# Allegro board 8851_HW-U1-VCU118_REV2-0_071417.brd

Outline 241.3 x 175.95 mm; copper layers: TOP, 02_GND, 03_SIG1, 04_GND, 05_SIG2, 06_GND, 07_SIG3, 08_GND, 09_PWR1, 10_GND, 11_PWR2, 12_PWR3, 13_GND, 14_SIG4, 15_GND, 16_SIG5, 17_GND, 18_SIG6, 19_GND, 20_SIG7, 21_GND, BOTTOM. Coordinates in mm from the lower left corner of the outline.
Outline path: 0,175.95 0,4.47 15.01,4.47 15.01,12.73 33.35,12.73 33.35,4.5 41.35,4.5 41.35,10.92 arc(43.18,12.75) 45.01,10.92 45.01,0.51 45.52,0 55.69,0 56.2,0.51 56.2,7.45 arc(57.15,8.41) 58.1,7.45 58.1,0.51 58.61,0 128.8,0 129.31,0.51 129.31,12.73 241.3,12.73 241.3,175.95 0,175.95

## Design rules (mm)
constraint set DEFAULT: min track width 0.152
net group 55N3111: nets 55N3111 VCC1V8_FET_SWITCH
net group 57N3711: nets 57N3711 VCC1V2_FET_SWITCH
net group DIFF_DX: nets DXN DXP
net group ENET_TD_A: nets ENET_TD_A_N ENET_TD_A_P
net group ENET_TD_B: nets ENET_TD_B_N ENET_TD_B_P
net group ENET_TD_C: nets ENET_TD_C_N ENET_TD_C_P
net group ENET_TD_D: nets ENET_TD_D_N ENET_TD_D_P
net group ETH_SGMII_CLK_PAIR: nets CLK_125MHZ_N CLK_125MHZ_P
net group FMCP_HSPC_GBT0_0: nets FMCP_HSPC_GBT0_0_N FMCP_HSPC_GBT0_0_P
net group FMCP_HSPC_GBT0_0_C: nets FMCP_HSPC_GBT0_0_C_N FMCP_HSPC_GBT0_0_C_P
net group FMCP_HSPC_GBT0_1: nets FMCP_HSPC_GBT0_1_N FMCP_HSPC_GBT0_1_P
net group FMCP_HSPC_GBT0_1_C: nets FMCP_HSPC_GBT0_1_C_N FMCP_HSPC_GBT0_1_C_P
net group FMCP_HSPC_GBT1_0: nets FMCP_HSPC_GBT1_0_N FMCP_HSPC_GBT1_0_P
net group FMCP_HSPC_GBT1_0_C: nets FMCP_HSPC_GBT1_0_C_N FMCP_HSPC_GBT1_0_C_P
net group FMCP_HSPC_GBT1_1: nets FMCP_HSPC_GBT1_1_N FMCP_HSPC_GBT1_1_P
net group FMCP_HSPC_GBT1_1_C: nets FMCP_HSPC_GBT1_1_C_N FMCP_HSPC_GBT1_1_C_P
net group FMCP_HSPC_GBT1_2: nets FMCP_HSPC_GBT1_2_N FMCP_HSPC_GBT1_2_P
net group FMCP_HSPC_GBT1_2_C: nets FMCP_HSPC_GBT1_2_C_N FMCP_HSPC_GBT1_2_C_P
net group FMCP_HSPC_GBT1_3: nets FMCP_HSPC_GBT1_3_N FMCP_HSPC_GBT1_3_P
net group FMCP_HSPC_GBT1_3_C: nets FMCP_HSPC_GBT1_3_C_N FMCP_HSPC_GBT1_3_C_P
net group FMCP_HSPC_GBT1_4: nets FMCP_HSPC_GBT1_4_N FMCP_HSPC_GBT1_4_P
net group FMCP_HSPC_GBT1_4_C: nets FMCP_HSPC_GBT1_4_C_N FMCP_HSPC_GBT1_4_C_P
net group FMCP_HSPC_GBT1_5: nets FMCP_HSPC_GBT1_5_N FMCP_HSPC_GBT1_5_P
net group FMCP_HSPC_GBT1_5_C: nets FMCP_HSPC_GBT1_5_C_N FMCP_HSPC_GBT1_5_C_P
net group FMCP_HSPC_GBTCLK0_M2C_C_N: nets FMCP_HSPC_GBTCLK0_M2C_C_N FMCP_HSPC_GBTCLK0_M2C_N
net group FMCP_HSPC_GBTCLK0_M2C_C_P: nets FMCP_HSPC_GBTCLK0_M2C_C_P FMCP_HSPC_GBTCLK0_M2C_P
net group FMCP_HSPC_GBTCLK2_M2C_C_N: nets FMCP_HSPC_GBTCLK2_M2C_C_N FMCP_HSPC_GBTCLK2_M2C_N
net group FMCP_HSPC_GBTCLK2_M2C_C_P: nets FMCP_HSPC_GBTCLK2_M2C_C_P FMCP_HSPC_GBTCLK2_M2C_P
net group FMCP_HSPC_REFCLK_M2C: nets FMCP_HSPC_REFCLK_M2C_N FMCP_HSPC_REFCLK_M2C_P
net group FPGA_EMCCLK: nets FPGA_EMCCLK FPGA_EMCCLK_R
net group I2C0_EEPROM_BUS: nets IIC_EEPROM_SCL IIC_EEPROM_SDA
net group IIC_FMC_HPC0_BUS: nets FMCP_HSPC_IIC_SCL FMCP_HSPC_IIC_SDA
net group IIC_FMC_HPC1_BUS: nets FMC_HPC1_IIC_SCL FMC_HPC1_IIC_SDA
net group IIC_MAIN2_BUS: nets IIC_MAIN_SCL IIC_MAIN_SDA
net group IIC_QSFP1_BUS: nets QSFP1_IIC_SCL QSFP1_IIC_SDA
net group IIC_QSFP2_BUS: nets QSFP2_IIC_SCL QSFP2_IIC_SDA
net group IIC_SI5324_BUS: nets SI5328_SCL SI5328_SDA
net group IIC_SYSMON_BUS: nets SYSMON_SCL SYSMON_SDA
net group MGT223_REFCLK1: nets MGT223_REFCLK1_N MGT233_REFCLK1_P
net group MGT226_CLK0: nets MGT226_CLK0_N MGT226_CLK0_P
net group MGT226_REFCLK0: nets MGT226_REFCLK0_N MGT226_REFCLK0_P
net group MGT233_CLK1: nets MGT233_CLK1_N MGT233_CLK1_P
net group MGT_SI570_CLOCK3_C_N: nets MGT_SI570_CLOCK3_C_N MGT_SI570_CLOCK3_N
net group MGT_SI570_CLOCK3_C_P: nets MGT_SI570_CLOCK3_C_P MGT_SI570_CLOCK3_P
net group PCIE_FMCP_HSPC_GBTCLK1_M2C: nets FMCP_HSPC_GBTCLK1_M2C_N FMCP_HSPC_GBTCLK1_M2C_P
net group PCIE_FMCP_HSPC_GBTCLK3_M2C: nets FMCP_HSPC_GBTCLK3_M2C_N FMCP_HSPC_GBTCLK3_M2C_P
net group PCIE_FMCP_HSPC_GBTCLK4_M2C: nets FMCP_HSPC_GBTCLK4_M2C_N FMCP_HSPC_GBTCLK4_M2C_P
net group PCIE_FMCP_HSPC_GBTCLK5_M2C: nets FMCP_HSPC_GBTCLK5_M2C_N FMCP_HSPC_GBTCLK5_M2C_P
net group PCIE_FMCP_HSPC_REFCLK_C2M: nets FMCP_HSPC_REFCLK_C2M_N FMCP_HSPC_REFCLK_C2M_P
net group PCIE_FMCP_HSPC_SYNC_C2M: nets FMCP_HSPC_SYNC_C2M_N FMCP_HSPC_SYNC_C2M_P
net group PCIE_FMCP_HSPC_SYNC_M2C: nets FMCP_HSPC_SYNC_M2C_N FMCP_HSPC_SYNC_M2C_P
net group PCIE_PCIE_CLK1: nets PCIE_CLK1_N PCIE_CLK1_P
net group PCIE_PCIE_CLK1_C: nets PCIE_CLK1_C_N PCIE_CLK1_C_P
net group PCIE_PCIE_CLK2: nets PCIE_CLK2_N PCIE_CLK2_P
net group PCIE_PCIE_CLK2_C: nets PCIE_CLK2_C_N PCIE_CLK2_C_P
net group PCIE_PCIE_CLK_Q0: nets PCIE_CLK_Q0_N PCIE_CLK_Q0_P
net group PCIE_PHY1_SGMII_CLK: nets PHY1_SGMII_CLK_N PHY1_SGMII_CLK_P
net group PCIE_PHY1_SGMII_CLK_C: nets PHY1_SGMII_CLK_C_N PHY1_SGMII_CLK_C_P
net group PCIE_PHY1_SGMII_OUT: nets PHY1_SGMII_OUT_N PHY1_SGMII_OUT_P
net group PCIE_PHY1_SGMII_OUT_C: nets PHY1_SGMII_OUT_C_N PHY1_SGMII_OUT_C_P
net group PCIE_SIT9122: nets SIT9122_N SIT9122_P
net group PCIE_TX0_C_N: nets PCIE_TX0_C_N PCIE_TX0_N
net group PCIE_TX0_C_P: nets PCIE_TX0_C_P PCIE_TX0_P
net group PCIE_TX1_C_N: nets PCIE_TX1_C_N PCIE_TX1_N
net group PCIE_TX1_C_P: nets PCIE_TX1_C_P PCIE_TX1_P
net group PCIE_TX2_C_N: nets PCIE_TX2_C_N PCIE_TX2_N
net group PCIE_TX2_C_P: nets PCIE_TX2_C_P PCIE_TX2_P
net group PCIE_TX3_C_N: nets PCIE_TX3_C_N PCIE_TX3_N
net group PCIE_TX3_C_P: nets PCIE_TX3_C_P PCIE_TX3_P
net group PCIE_TX4_C_N: nets PCIE_TX4_C_N PCIE_TX4_N
net group PCIE_TX4_C_P: nets PCIE_TX4_C_P PCIE_TX4_P
net group PCIE_TX5_C_N: nets PCIE_TX5_C_N PCIE_TX5_N
net group PCIE_TX5_C_P: nets PCIE_TX5_C_P PCIE_TX5_P
net group PCIE_TX6_C_N: nets PCIE_TX6_C_N PCIE_TX6_N
net group PCIE_TX6_C_P: nets PCIE_TX6_C_P PCIE_TX6_P
net group PCIE_TX7_C_N: nets PCIE_TX7_C_N PCIE_TX7_N
net group PCIE_TX7_C_P: nets PCIE_TX7_C_P PCIE_TX7_P
net group PCIE_TX8_C_N: nets PCIE_TX8_C_N PCIE_TX8_N
net group PCIE_TX8_C_P: nets PCIE_TX8_C_P PCIE_TX8_P
net group PCIE_TX9_C_N: nets PCIE_TX9_C_N PCIE_TX9_N
net group PCIE_TX9_C_P: nets PCIE_TX9_C_P PCIE_TX9_P
net group PCIE_TX10_C_N: nets PCIE_TX10_C_N PCIE_TX10_N
net group PCIE_TX10_C_P: nets PCIE_TX10_C_P PCIE_TX10_P
net group PCIE_TX11_C_N: nets PCIE_TX11_C_N PCIE_TX11_N
net group PCIE_TX11_C_P: nets PCIE_TX11_C_P PCIE_TX11_P
net group PCIE_TX12_C_N: nets PCIE_TX12_C_N PCIE_TX12_N
net group PCIE_TX12_C_P: nets PCIE_TX12_C_P PCIE_TX12_P
net group PCIE_TX13_C_N: nets PCIE_TX13_C_N PCIE_TX13_N
net group PCIE_TX13_C_P: nets PCIE_TX13_C_P PCIE_TX13_P
net group PCIE_TX14_C_N: nets PCIE_TX14_C_N PCIE_TX14_N
net group PCIE_TX14_C_P: nets PCIE_TX14_C_P PCIE_TX14_P
net group PCIE_TX15_C_N: nets PCIE_TX15_C_N PCIE_TX15_N
net group PCIE_TX15_C_P: nets PCIE_TX15_C_P PCIE_TX15_P
net group PCIE_USER_SI570_CLOCK1: nets USER_SI570_CLOCK1_N USER_SI570_CLOCK1_P
net group PCIE_VCCINT_VIN: nets VCCINT_VIN_N VCCINT_VIN_P
net group PCIE_VCCINT_VIN_R: nets VCCINT_VIN_R_N VCCINT_VIN_R_P
net group PHY1_SGMII_IN_C_N: nets PHY1_SGMII_IN_C_N PHY1_SGMII_IN_N
net group PHY1_SGMII_IN_C_P: nets PHY1_SGMII_IN_C_P PHY1_SGMII_IN_P
net group PMBUS: nets PMBUS_SCL PMBUS_SDA
net group QSFP_SI570_CLOCK_C_N: nets QSFP_SI570_CLOCK_C_N QSFP_SI570_CLOCK_N
net group QSFP_SI570_CLOCK_C_P: nets QSFP_SI570_CLOCK_C_P QSFP_SI570_CLOCK_P
net group SI5328_CLOCK2_C: nets SI5328_CLOCK2_C_N SI5328_CLOCK2_C_P
net group SI5328_OUT2_PAIR: nets SI5328_CLOCK2_N SI5328_CLOCK2_P
net group SMA_USER_CLOCK: nets USER_SMA_CLOCK_N USER_SMA_CLOCK_P
net group SYSCTLR_CLK: nets SYSCTLR_CLK SYSCTLR_CLK_R
net group SYSCTLR_UART: nets SYSCTLR_UART_RX SYSCTLR_UART_TX
net group SYSMON_VN: nets SYSMON_VN SYSMON_VP
net group USB_JTAG_CONNECTOR_PAIR: nets USB_JTAG_DATA_N USB_JTAG_DATA_P
net group USB_UART_DATA_N: nets USB_UART_DATA_N USB_UART_DATA_P
net group USER_SI570_0_CLOCK: nets USER_SI570_0_CLOCK_SCL USER_SI570_0_CLOCK_SDA
net group USER_SI570_2_CLOCK: nets USER_SI570_2_CLOCK_SCL USER_SI570_2_CLOCK_SDA
net group USER_SI570_CLOCK: nets USER_SI570_CLOCK_N USER_SI570_CLOCK_P
net group UTIL_1V35_SNS: nets UTIL_1V35_SNS_N UTIL_1V35_SNS_P
net group UTIL_3V3_SNS: nets UTIL_3V3_SNS_N UTIL_3V3_SNS_P
net group VADJ_1V8_FPGA_VIN: nets VADJ_1V8_FPGA_VIN VADJ_1V8_VIN
net group VCC1V8_FPGA_VIN: nets VCC1V8_FPGA_VIN VCC1V8_VIN
net group VCCINT_SNS: nets VCCINT_SNS_N VCCINT_SNS_P
net group 32N6304: nets 32N6304
net group 52N6304: nets 52N6304
net group DEFAULT: nets IIC_MUX_RESET_B PCIE_PERST PCIE_PERST_LS PCIE_PRSNT_B PCIE_PRSNT_X1 PCIE_PRSNT_X4 PCIE_PRSNT_X8 PCIE_WAKE_B PCIE_WAKE_B_LS SM_FAN_PWM SM_FAN_TACH
net group FIREFLY_RX: nets FIREFLY_RX1_N FIREFLY_RX1_P FIREFLY_RX2_N FIREFLY_RX2_P FIREFLY_RX3_N FIREFLY_RX3_P FIREFLY_RX4_N FIREFLY_RX4_P
net group FIREFLY_TX: nets FIREFLY_TX1_N FIREFLY_TX1_P FIREFLY_TX2_N FIREFLY_TX2_P FIREFLY_TX3_N FIREFLY_TX3_P FIREFLY_TX4_N FIREFLY_TX4_P
net group FMC_HPC0_CLK_BUS: nets FMCP_HSPC_CLK0_M2C_N FMCP_HSPC_CLK0_M2C_P FMCP_HSPC_CLK1_M2C_N FMCP_HSPC_CLK1_M2C_P
net group FMC_HPC0_GBTCLK0_M2C: nets FMCP_HSPC_GBTCLK3_M2C_C_N FMCP_HSPC_GBTCLK3_M2C_C_P FMCP_HSPC_GBTCLK4_M2C_C_N FMCP_HSPC_GBTCLK4_M2C_C_P FMCP_HSPC_GBTCLK5_M2C_C_N FMCP_HSPC_GBTCLK5_M2C_C_P
net group FMC_HPC0_LA_BUS: nets FMCP_HSPC_LA00_CC_N FMCP_HSPC_LA00_CC_P FMCP_HSPC_LA01_CC_N FMCP_HSPC_LA01_CC_P FMCP_HSPC_LA02_N FMCP_HSPC_LA02_P FMCP_HSPC_LA18_CC_N FMCP_HSPC_LA18_CC_P
net group FMC_HPC1_CLK_BUS: nets FMC_HPC1_CLK0_M2C_N FMC_HPC1_CLK0_M2C_P FMC_HPC1_CLK1_M2C_N FMC_HPC1_CLK1_M2C_P
net group JTAG_TCK_TDI: nets JTAG_TCK JTAG_TDI JTAG_TMS
net group MG_MUX_TO_CARD_SDIO: nets SDIO_CONN_CLK SDIO_CONN_CMD SDIO_CONN_DATA0 SDIO_CONN_DATA1 SDIO_CONN_DATA2 SDIO_CONN_DATA3
net group MGT_SI570_CLOCK1_PAIR: nets MGT_SI570_CLOCK1_C_N MGT_SI570_CLOCK1_C_P MGT_SI570_CLOCK1_N MGT_SI570_CLOCK1_P
net group MGT_SI570_CLOCK2_PAIR: nets MGT_SI570_CLOCK2_C_N MGT_SI570_CLOCK2_C_P MGT_SI570_CLOCK2_N MGT_SI570_CLOCK2_P
net group PCIE_RX_PAIR: nets PCIE_RX0_N PCIE_RX0_P PCIE_RX1_N PCIE_RX1_P PCIE_RX2_N PCIE_RX2_P PCIE_RX3_N PCIE_RX3_P PCIE_RX4_N PCIE_RX4_P PCIE_RX5_N PCIE_RX5_P PCIE_RX6_N PCIE_RX6_P PCIE_RX7_N PCIE_RX7_P PCIE_RX8_N PCIE_RX8_P PCIE_RX9_N PCIE_RX9_P PCIE_RX10_N PCIE_RX10_P PCIE_RX11_N PCIE_RX11_P PCIE_RX12_N PCIE_RX12_P PCIE_RX13_N PCIE_RX13_P PCIE_RX14_N PCIE_RX14_P PCIE_RX15_N PCIE_RX15_P
net group PWR_GND: nets 17N2123 21N4739 40N4221 41N97 52N3398 55N3098 55N3099 55N3100 55N3101 55N3102 55N3103 55N3104 55N3109 55N3110 55N3112 55N3113 55N3114 55N3115 55N3116 55N3155 55N3156 56N1406 56N1407 56N1411 56N1412 56N1413 56N1414 56N1415 56N1416 56N1425 56N1426 56N1427 56N1428 56N1429 56N1430 56N1431 56N1432 56N1434 56N2929 57N3698 57N3699 57N3700 57N3701 57N3702 57N3703 57N3704 57N3709 57N3710 57N3712 57N3713 57N3714 57N3715 57N3716 57N3731 57N3732 61N5741 61N5742 61N5743 61N5744 61N5745 61N5746 61N5747 61N5752 61N5753 61N5754 61N5755 61N5756 61N5757 61N5758 61N5761 61N5762 61N5776 63N4710 64N651 77N2783 77N2784 77N2785 77N2786 77N2787 77N2788 77N2789 77N2790 77N2796 77N2797 77N2798 77N2799 77N2800 77N2801 77N2802 77N2803 77N2808 77N4651 77N4678 5336N2099 AGND9 AGND10 COMBINED_PGOOD CPU_RESET DDR4_C1_VREFA DDR4_C1_VREFB DDR4_C1_VREFC DDR4_C1_VREFE DDR4_C2_VREFA DDR4_C2_VREFB DDR4_C2_VREFC DDR4_C2_VREFE FMC_VADJ_ON FPGA_PROG_B FPGA_VBATT MGTAVCC_PGOOD MGTAVCC_SLAVE_1V8 MGTAVCC_VDD_MASTER MGTAVTT_PGOOD MGTAVTT_SLAVE_1V8 MGTAVTT_VDD_MASTER REG_SYNC SYS_1V0_PGOOD SYS_1V0_POR_B SYS_1V8_POR_B SYS_2V5_PGOOD SYS_2V5_POR_B USB_JTAG_FLTR USB_JTAG_GND USB_JTAG_VBUS USB_VBUS USB_VBUS_GND UTIL_1V35_DH_R UTIL_1V35_DL UTIL_1V35_FET_SWITCH UTIL_1V35_PGOOD UTIL_1V35_TEMPX UTIL_3V3_DH_R UTIL_3V3_DL UTIL_3V3_PGOOD UTIL_3V3_TEMPX VAD_1V8_TEMPX VADJ_1V8_EN VADJ_1V8_FET_SWITCH VADJ_1V8_PGOOD VADJ_DH_R VADJ_DL VCC1V2_DH_R VCC1V2_DL VCC1V2_PGOOD VCC1V2_TEMPX VCC1V8_DH_R VCC1V8_DL VCC1V8_PGOOD VCC1V8_TEMPX VCCINT VCCINT_PGOOD VCCINTIO_BRAM_PGOOD VREF_70
net group QSFP_RX: nets QSFP1_RX1_N QSFP1_RX1_P QSFP1_RX2_N QSFP1_RX2_P QSFP1_RX3_N QSFP1_RX3_P QSFP1_RX4_N QSFP1_RX4_P QSFP2_RX1_N QSFP2_RX1_P QSFP2_RX2_N QSFP2_RX2_P QSFP2_RX3_N QSFP2_RX3_P QSFP2_RX4_N QSFP2_RX4_P
net group QSFP_TX: nets QSFP1_TX1_N QSFP1_TX1_P QSFP1_TX2_N QSFP1_TX2_P QSFP1_TX3_N QSFP1_TX3_P QSFP1_TX4_N QSFP1_TX4_P QSFP2_TX1_N QSFP2_TX1_P QSFP2_TX2_N QSFP2_TX2_P QSFP2_TX3_N QSFP2_TX3_P QSFP2_TX4_N QSFP2_TX4_P
net group REC_CLOCK_PAIR: nets QSFP1_RECCLK_C_N QSFP1_RECCLK_C_P QSFP1_RECCLK_N QSFP1_RECCLK_P QSFP2_RECCLK_C_N QSFP2_RECCLK_C_P QSFP2_RECCLK_N QSFP2_RECCLK_P
net group RLD3_C3_ADDR: nets RLD3_C3_72B_A0
net group RLD3_C3_ADDR_SE: nets RLD3_C3_72B_A20
net group SI570_OUTPUT_PAIR: nets SI570_0_OUTPUT_N SI570_0_OUTPUT_P SI570_1_OUTPUT_N SI570_1_OUTPUT_P
net group SI5328_OUT1_PAIR: nets SI5328_CLOCK1_C_N SI5328_CLOCK1_C_P SI5328_CLOCK1_N SI5328_CLOCK1_P
net group SYSCLK_300_PAIR: nets SYSCLK1_300_C_N SYSCLK1_300_C_P SYSCLK1_300_N SYSCLK1_300_P SYSCLK2_300_N SYSCLK2_300_P SYSCLK_300_N SYSCLK_300_P
net group SYSCTLR_SDIO: nets SDIO_CD
net group USB_UART_BUS: nets USB_UART_CTS USB_UART_RTS USB_UART_RX

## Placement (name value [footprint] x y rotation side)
B1  TS518FE-FL35E  [BAT_TS518_TS621_DUAL]  176.1 25.18 270 top
C1  0.1UF  [0402]  54.29 53.15 90 bottom
C2  0.1UF  [0402]  117.86 58.86 270 bottom
C3  22UF  [1206]  42.6 56.19 180 bottom
C4  DNP  [C402-25]  117.24 55.35 180 bottom
C5  0.1UF  [0402]  50.16 83.11 270 bottom
C6  0.1UF  [0402]  37.47 87.05 0 bottom
C7  0.1UF  [0402]  50.55 95.3 0 bottom
C8  22UF  [0603]  51.69 83.11 270 bottom
C9  0.01UF  [0402]  108.29 28.18 270 top
C10  0.01UF  [0402]  107.15 28.18 270 top
C11  22UF  [0603]  36.96 88.44 0 bottom
C12  22UF  [0603]  41.66 95.55 180 bottom
C13  0.01UF  [0402]  114.71 124.31 270 top
C14  0.01UF  [0402]  115.98 124.31 270 top
C15  0.1UF  [0402]  119.08 121.08 90 bottom
C16  0.01UF  [0402]  126.95 120.6 0 top
C17  0.22UF  [0402]  95.23 17.72 90 top
C18  0.22UF  [0402]  94.09 17.72 90 top
C19  0.22UF  [0402]  90.88 15.87 90 top
C20  0.22UF  [0402]  89.73 15.87 90 top
C21  0.22UF  [0402]  86.52 17.47 90 top
C22  0.22UF  [0402]  85.38 17.47 90 top
C23  0.1UF  [0402]  90.17 21.31 0 top
C24  0.1UF  [0402]  90.17 22.45 0 top
C25  0.1UF  [0402]  79.88 23.04 0 top
C26  0.1UF  [0402]  82.68 25.96 0 bottom
C27  0.1UF  [0402]  87.88 25.32 180 bottom
C28  0.1UF  [0402]  79.88 21.89 0 top
C29  0.22UF  [0402]  82.12 16 90 top
C30  0.22UF  [0402]  80.97 16 90 top
C31  0.22UF  [0402]  99.72 17.72 90 top
C32  0.22UF  [0402]  98.58 17.72 90 top
C33  0.22UF  [0402]  102.58 16.12 90 top
C34  0.22UF  [0402]  103.72 16.12 90 top
C35  0.22UF  [0402]  106.58 17.75 90 top
C36  0.22UF  [0402]  107.72 17.75 90 top
C37  0.22UF  [0402]  110.58 16.12 90 top
C38  0.22UF  [0402]  111.72 16.12 90 top
C39  0.1UF  [0402]  35 65.7 0 bottom
C40  0.1UF  [0402]  35.65 70.78 0 bottom
C41  0.1UF  [0402]  53.88 149.61 270 bottom
C42  0.22UF  [0402]  114.58 17.85 90 top
C43  0.22UF  [0402]  115.72 17.85 90 top
C44  0.22UF  [0402]  118.58 16.12 90 top
C45  0.22UF  [0402]  119.72 16.12 90 top
C46  0.22UF  [0402]  123.47 17.85 90 top
C47  0.22UF  [0402]  124.61 17.85 90 top
C48  0.22UF  [0402]  126.58 16.12 90 top
C49  0.22UF  [0402]  127.72 16.12 90 top
C50  0.22UF  [0402]  75.83 18.16 90 top
C51  0.22UF  [0402]  76.98 18.16 90 top
C52  0.22UF  [0402]  71.47 15.63 90 top
C53  0.1UF  [0402]  143.38 113.72 270 top
C54  0.1UF  [0402]  12.1 64.36 180 top
C55  0.1UF  [0402]  3.48 70.99 270 bottom
C56  0.22UF  [0402]  72.61 15.63 90 top
C57  0.1UF  [0402]  7.09 74.93 180 bottom
C58  0.22UF  [0402]  68.47 19.43 90 top
C59  0.22UF  [0402]  69.61 19.43 90 top
C60  0.22UF  [0402]  64.1 16.12 90 top
C61  0.22UF  [0402]  65.25 16.12 90 top
C62  0.1UF  [0402]  52.07 76.25 270 bottom
C63  0.1UF  [0402]  50.8 76.25 270 bottom
C64  0.1UF  [0402]  18.9 90.46 90 bottom
C65  0.1UF  [0402]  61.77 45.97 90 bottom
C66  0.1UF  [0402]  56.34 61.47 180 bottom
C67  0.01UF  [0402]  64.09 43.94 0 bottom
C68  10UF  [1210]  17.8 91.69 180 top
C69  0.1UF  [0402]  59.54 45.57 180 bottom
C70  0.1UF  [0402]  31.27 83.11 90 bottom
C71  0.1UF  [0402]  225.55 72.45 180 top
C72  0.1UF  [0402]  222.76 68.63 270 bottom
C73  0.1UF  [0402]  231.39 90.35 180 bottom
C74  0.1UF  [0402]  233.55 79.04 0 bottom
C75  0.1UF  [0402]  56.68 138.94 0 bottom
C76  0.1UF  [0402]  38.92 76.7 270 bottom
C77  0.1UF  [0402]  32.91 133.59 90 top
C78  10UF  [0603]  37.42 146.86 0 top
C79  10UF  [0603]  26.67 144.11 270 bottom
C80  10UF  [0603]  40.26 145.59 270 top
C81  0.01UF  [0402]  201.13 16.04 90 top
C82  0.01UF  [0402]  37.4 146.9 0 bottom
C83  0.01UF  [0402]  39.75 138.86 180 bottom
C84  0.01UF  [0402]  35.43 142.54 270 bottom
C85  0.1UF  [0402]  34.2 133.59 90 top
C86  0.1UF  [0402]  43.68 135.43 180 top
C87  0.1UF  [0402]  44.19 133.59 90 top
C88  0.01UF  [0402]  102.34 27.42 270 top
C89  0.01UF  [0402]  101.19 27.42 270 top
C90  0.1UF  [0402]  38.99 132.32 90 top
C91  0.1UF  [0402]  146.78 123.31 0 bottom
C92  0.1UF  [0402]  145.92 122.1 270 top
C93  0.1UF  [0402]  37.84 132.32 90 top
C94  0.01UF  [0402]  127.29 31.8 270 top
C95  0.01UF  [0402]  126.02 31.8 270 top
C96  0.1UF  [0402]  50.52 73.99 90 bottom
C97  0.1UF  [0402]  189.23 153.97 180 top
C98  0.1UF  [0402]  186.27 144.17 90 bottom
C99  0.1UF  [0402]  39.19 73.86 270 bottom
C100  0.01UF  [0402]  118.03 100.51 90 top
C101  0.01UF  [0402]  119.58 100.51 90 top
C102  0.01UF  [0402]  64.09 42.67 0 bottom
C103  1UF  [0402]  33.91 137.08 0 bottom
C104  0.1UF  [0402]  86.69 104.79 270 top
C105  0.1UF  [0402]  80.59 105.04 270 top
C106  0.1UF  [0402]  74.24 105.04 270 top
C107  0.1UF  [0402]  67.89 105.04 270 top
C108  0.1UF  [0402]  73.22 101.61 270 top
C109  1UF  [0402]  37.33 136.58 90 bottom
C110  1UF  [0402]  39.75 140.11 180 bottom
C111  1UF  [0402]  37.08 142.54 270 bottom
C112  1UF  [0402]  40.26 145.59 270 bottom
C113  1UF  [0402]  38.6 142.54 270 bottom
C114  1UF  [0402]  40.13 137.17 270 bottom
C115  1UF  [0402]  32.26 133.4 90 bottom
C116  1UF  [0402]  33.78 138.86 0 bottom
C117  0.1UF  [0402]  222.88 65.71 90 top
C118  0.01UF  [0402]  64.09 41.4 0 bottom
C119  0.01UF  [0402]  64.09 40.13 0 bottom
C120  0.1UF  [0402]  226.95 69.52 90 top
C121  0.1UF  [0402]  217.64 85.98 90 top
C122  0.1UF  [0402]  56.34 36.15 180 bottom
C123  0.1UF  [0402]  62.38 24.52 270 bottom
C124  1UF  [0603]  189.01 134.8 270 bottom
C125  0.1UF  [0402]  206.67 57.86 270 bottom
C126  0.1UF  [0402]  55.25 76.12 270 bottom
C127  0.1UF  [0402]  194.26 60.11 180 bottom
C128  0.1UF  [0402]  195.96 61.77 90 top
C129  0.1UF  [0402]  33.52 146.84 270 top
C130  2.2UF  [0402]  206.98 63.17 90 bottom
C131  100UF  [1210]  208.96 58.3 90 top
C132  10UF  [0603]  136.62 18.11 180 bottom
C133  0.1UF  [0402]  43.67 138.68 0 bottom
C134  0.1UF  [0402]  43.67 138.93 0 top
C135  0.1UF  [0402]  38.44 136.58 90 bottom
C136  0.1UF  [0402]  32.26 135.57 270 bottom
C137  0.1UF  [0402]  34.29 142.54 270 bottom
C138  0.1UF  [0402]  58.55 89.97 180 top
C139  0.1UF  [0402]  39.62 142.54 270 bottom
C140  0.1UF  [0402]  33.78 140 0 bottom
C141  0.1UF  [0402]  36.19 136.58 90 bottom
C142  0.1UF  [0402]  30.1 135.56 0 bottom
C143  18PF  [0402]  31.75 143.9 90 top
C144  18PF  [0402]  29.15 147.35 0 top
C145  10UF  [0603]  217.87 63.12 0 bottom
C146  2.2UF  [0805]  216.63 70 90 top
C147  22UF  [1210]  202.53 69.9 0 top
C148  22UF  [1210]  202.53 73.2 0 top
C149  0.1UF  [0402]  217.64 83.82 270 top
C150  0.1UF  [0402]  207.82 81.02 180 top
C151  22UF  [1206]  222.97 83.06 0 top
C152  0.1UF  [0402]  192.23 118.65 270 bottom
C153  100UF  [1206]  170.81 121.34 180 bottom
C154  0.1UF  [0402]  192.74 120.68 0 bottom
C155  0.1UF  [0402]  172.82 70.27 180 top
C156  47UF  [1210]  65.15 47.93 90 top
C157  0.1UF  [0402]  174.39 68.61 180 bottom
C158  0.1UF  [0402]  135.05 130.29 90 top
C159  4.7UF  [0402]  84.07 82.35 180 top
C160  4.7UF  [0402]  151.89 47.17 0 bottom
C161  47UF  [1210]  144.14 109.4 90 top
C162  0.1UF  [0402]  133.68 129.04 90 bottom
C163  100UF  [1206]  178.94 121.21 180 bottom
C164  100UF  [1206]  121.67 104.06 180 bottom
C165  100UF  [1206]  121.67 104.06 180 top
C166  47UF  [1210]  178.05 66.22 0 top
C167  47UF  [1210]  134.49 125.91 180 top
C168  47UF  [1210]  148.72 29.26 180 top
C169  47UF  [1210]  131.06 99.87 0 top
C170  47UF  [1210]  167.89 99.87 0 top
C171  47UF  [1210]  125.35 131.11 90 top
C172  1UF  [0603]  138.72 28.18 0 bottom
C173  1UF  [0603]  203.93 67.23 90 bottom
C174  100UF  [1210]  183.98 142.84 270 top
C175  0.01UF  [0402]  209.39 69.01 180 bottom
C176  4.7UF  [0402]  115.32 31.8 270 top
C177  4.7UF  [0402]  111.25 31.8 270 top
C178  4.7UF  [0402]  111.25 31.8 270 bottom
C179  4.7UF  [0402]  112.65 31.8 270 bottom
C180  4.7UF  [0402]  112.65 31.8 270 top
C181  4.7UF  [0402]  114.05 31.8 270 top
C182  4.7UF  [0402]  114.05 31.8 270 bottom
C183  DNP  [0402]  141.19 27.76 90 bottom
C184  0.22UF  [0402]  208.6 59.43 270 bottom
C185  2200PF  [0402]  214.85 57.07 0 top
C186  0.15UF  [0402]  213.71 69.01 180 bottom
C187  0.15UF  [0402]  211.55 69.01 180 bottom
C188  100PF  [0402]  216.91 61.47 0 bottom
C189  4.7UF  [0603]  207.08 70.36 90 bottom
C190  0.022UF  [0402]  46.69 130.89 0 top
C191  1UF  [0402]  47.7 141.66 180 top
C192  4.7UF  [0805]  49.73 136.86 90 top
C193  22UF  [1206]  222.97 83.06 0 bottom
C194  100UF  [1210]  201.25 39.72 180 top
C195  22UF  [1206]  222.97 85.98 0 top
C196  100UF  [1206]  177.3 91.11 180 top
C197  100UF  [1206]  177.3 87.55 180 top
C198  0.01UF  [0402]  113.38 100.51 90 top
C199  0.01UF  [0402]  114.93 100.51 90 top
C200  0.01UF  [0402]  107.19 100.51 90 top
C201  0.01UF  [0402]  108.73 100.51 90 top
C202  0.01UF  [0402]  105.64 100.51 90 bottom
C203  0.01UF  [0402]  107.19 100.51 90 bottom
C204  0.01UF  [0402]  99.09 22.73 0 bottom
C205  47UF  [1210]  185.8 45.39 90 top
C206  470UF  [TANT_D]  152.61 107.38 0 top
C207  0.01UF  [0402]  126.95 121.87 0 top
C208  0.01UF  [0402]  126.95 123.14 0 top
C209  0.01UF  [0402]  126.95 124.41 0 top
C210  0.01UF  [0402]  128.02 112 180 top
C211  0.01UF  [0402]  128.02 110.86 180 top
C212  0.01UF  [0402]  116.09 114.6 180 top
C213  0.01UF  [0402]  116.09 113.46 180 top
C214  0.01UF  [0402]  116.09 116.89 180 top
C215  22UF  [1210]  190.79 133.02 180 top
C216  22UF  [1210]  190.79 129.72 180 top
C217  0.01UF  [0402]  116.09 115.75 180 top
C218  0.01UF  [0402]  116.09 119.18 180 top
C219  0.01UF  [0402]  116.09 118.03 180 top
C220  0.01UF  [0402]  127.13 113.46 180 top
C221  0.01UF  [0402]  127.13 114.6 180 top
C222  0.01UF  [0402]  127.13 115.75 180 top
C223  0.01UF  [0402]  127.13 116.89 180 top
C224  0.01UF  [0402]  127.13 118.03 180 top
C225  0.01UF  [0402]  127.13 119.18 180 top
C226  1UF  [0603]  219.16 82.8 270 top
C227  1UF  [0603]  219.16 85.98 90 top
C228  1UF  [0402]  210.14 82.04 270 top
C229  DNP  [0402]  236.9 103.28 270 top
C230  470UF  [TANT_D]  179.38 102.14 180 top
C231  0.22UF  [0402]  210.28 84.79 270 top
C232  1000PF  [0402]  217.64 81.66 270 top
C233  DNP  [0603]  208.55 84.51 270 top
C234  22UF  [0603]  36.96 91.24 180 bottom
C235  0.1UF  [0402]  37.47 89.84 180 bottom
C236  0.1UF  [0402]  121.44 116.61 270 bottom
C237  0.1UF  [0402]  27.1 157.18 90 top
C238  0.1UF  [0402]  27.08 153.9 90 top
C239  0.1UF  [0402]  54.1 76.12 270 bottom
C240  2200PF  [0402]  177.42 36.25 0 top
C241  0.01UF  [0402]  24.47 100.28 90 top
C242  10UF  [1210]  220.35 147.99 90 top
C243  0.01UF  [0402]  23.33 100.28 90 top
C244  0.01UF  [0402]  58.45 106.32 180 top
C245  0.01UF  [0402]  58.45 105.17 180 top
C246  47UF  [1210]  174.12 61.68 0 top
C247  47UF  [1210]  131.44 121.46 0 top
C248  47UF  [1210]  158.12 103.12 0 top
C249  4.7UF  [0402]  155.32 55.42 270 bottom
C250  4.7UF  [0402]  154.94 58.09 90 bottom
C251  4.7UF  [0402]  148.97 99.62 90 top
C252  4.7UF  [0402]  151.89 51.8 0 bottom
C253  4.7UF  [0402]  153.92 63.3 90 bottom
C254  4.7UF  [0402]  150.75 99.62 90 top
C255  4.7UF  [0402]  151.89 52.85 0 bottom
C257  2.2UF  [0805]  176.31 132.03 270 top
C258  2.2UF  [0402]  185.96 138.86 270 bottom
C288  1UF  [0603]  60.09 152.75 270 bottom
C289  1UF  [0603]  51.98 158.93 180 bottom
C290  1UF  [0603]  58.07 152.75 270 bottom
C294  1UF  [0603]  88.27 29.01 0 top
C295  1UF  [0603]  6.86 73.33 180 bottom
C298  1UF  [0603]  219.71 142.67 0 top
C324  0.01UF  [0402]  109.73 22.15 90 top
C330  680UF  [TANT_X]  196.05 71.68 270 top
C331  4.7UF  [0402]  154.05 81.84 270 bottom
C334  4.7UF  [0402]  151.89 73.15 0 bottom
C346  1UF  [0603]  15.27 63.47 180 top
C348  4.7UF  [0402]  77.23 48.42 0 top
C349  4.7UF  [0402]  69.49 48.42 0 top
C350  4.7UF  [0402]  67.89 101.61 270 top
C351  4.7UF  [0402]  86.69 101.61 270 top
C352  4.7UF  [0402]  81.86 101.61 270 top
C353  4.7UF  [0402]  69.49 34.32 0 top
C354  4.7UF  [0402]  77.74 34.32 180 top
C356  4.7UF  [0402]  58.55 86.54 180 top
C358  DNP  [0402]  221.11 153.2 0 top
C369  0.15UF  [0402]  181.39 133.02 0 bottom
C370  0.01UF  [0402]  183.55 133.02 0 bottom
C406  0.22UF  [0402]  184.34 142.6 90 bottom
C423  10UF  [0603]  175.95 138.91 180 bottom
C434  0.068UF  [0402]  74.06 57.06 180 top
C435  0.068UF  [0402]  73.93 50.83 90 top
C436  0.068UF  [0402]  80.66 57.06 180 top
C437  0.068UF  [0402]  67.58 55.91 270 top
C438  0.068UF  [0402]  67.58 41.82 270 top
C439  0.068UF  [0402]  73.93 36.74 90 top
C440  0.068UF  [0402]  74.06 42.96 180 top
C441  0.068UF  [0402]  80.66 42.96 180 top
C451  1000PF  [0402]  64.13 87.07 90 bottom
C454  2200PF  [0402]  178.09 144.71 180 top
C460  680UF  [TANT_X]  78.36 139.54 180 top
C461  680UF  [TANT_X]  132.12 109.27 90 top
C462  680UF  [TANT_X]  111.29 109.77 0 top
C466  100PF  [0805]  113.91 162.55 180 bottom
C467  100PF  [0805]  51.98 162.7 180 bottom
C470  4.7UF  [0603]  11.71 64.36 180 bottom
C480  4.7UF  [0603]  185.86 131.67 270 bottom
C491  0.47UF  [0402]  72.79 48.46 0 top
C492  0.47UF  [0402]  75.2 48.42 0 top
C493  0.47UF  [0402]  78.49 57.04 180 top
C494  0.47UF  [0402]  71.77 57.06 180 top
C495  0.47UF  [0402]  81.3 33.94 270 top
C496  0.47UF  [0402]  78.49 42.94 180 top
C497  0.47UF  [0402]  71.77 42.96 180 top
C498  0.47UF  [0402]  75.2 34.32 0 top
C499  330UF  [CAPR_800_350]  199.99 135.05 180 top
C500  10UF  [0805]  88.27 30.78 0 top
C501  0.1UF  [0402]  172.21 41.99 180 bottom
C516  10UF  [0805]  61.51 93.35 180 top
C517  10UF  [0805]  61.51 91.21 180 top
C518  10UF  [0805]  61.51 93.35 180 bottom
C519  10UF  [0805]  62.31 84.83 180 top
C520  10UF  [0805]  62.31 82.81 180 top
C522  0.1UF  [0402]  137.01 114.37 0 bottom
C525  0.1UF  [0402]  190.97 170.96 180 bottom
C527  0.1UF  [0402]  207.5 144.83 270 top
C540  0.1UF  [0402]  129.79 15.07 90 bottom
C543  0.1UF  [0402]  14.25 66.78 270 bottom
C549  0.1UF  [0402]  221.11 154.47 0 top
C550  0.1UF  [0402]  204.09 146.86 180 top
C551  0.1UF  [0402]  207.14 146.86 180 top
C555  0.1UF  [0402]  69.87 57.06 0 top
C556  0.1UF  [0402]  71.24 44.61 0 top
C557  0.1UF  [0402]  71.06 47.24 180 top
C558  0.1UF  [0402]  71.24 30.51 0 top
C559  0.1UF  [0402]  71.06 33.15 180 top
C560  0.1UF  [0402]  69.87 42.96 0 top
C589  4.7UF  [0402]  94.31 100.51 90 top
C590  4.7UF  [0402]  84.07 86.16 180 top
C595  4.7UF  [0402]  94.31 100.51 90 bottom
C596  4.7UF  [0402]  84.07 48.18 180 top
C601  4.7UF  [0402]  142.37 31.67 270 bottom
C602  4.7UF  [0402]  84.07 50.72 180 top
C603  4.7UF  [0402]  79.23 48.42 180 top
C604  4.7UF  [0402]  80.15 33.94 270 top
C614  0.22UF  [0402]  118.11 30.66 270 bottom
C615  0.22UF  [0402]  122.68 100.51 90 bottom
C618  0.22UF  [0402]  118.11 30.66 270 top
C619  0.22UF  [0402]  96.34 100.89 180 top
C622  0.22UF  [0402]  109.47 31.8 270 top
C623  0.22UF  [0402]  121.13 100.51 90 bottom
C628  0.47UF  [0402]  99.39 100.51 90 top
C630  0.47UF  [0402]  119.51 30.66 270 top
C632  0.47UF  [0402]  99.39 100.51 90 bottom
C633  0.1UF  [0402]  132.46 15.54 90 bottom
C639  0.01UF  [0402]  83.26 92.62 0 top
C640  0.1UF  [0402]  126.79 139.66 180 bottom
C650  0.1UF  [0402]  174.05 20.07 90 top
C651  0.1UF  [0402]  172.78 20.07 90 top
C657  4.7UF  [0402]  84.07 89.84 180 top
C658  4.7UF  [0402]  84.07 81.08 180 top
C659  4.7UF  [0402]  84.07 88.7 180 top
C695  0.1UF  [0402]  71.24 58.71 0 top
C696  0.1UF  [0402]  71.06 61.34 180 top
C697  0.1UF  [0402]  69.87 71.15 0 top
C698  0.1UF  [0402]  67.58 90.98 90 top
C699  0.1UF  [0402]  71.63 90.71 0 top
C700  0.1UF  [0402]  69.87 99.35 0 top
C701  1UF  [0603]  107.95 24.31 90 bottom
C702  4.7UF  [0402]  77.74 62.52 180 top
C703  4.7UF  [0402]  69.49 62.52 0 top
C704  4.7UF  [0402]  80.15 62.14 270 top
C705  4.7UF  [0402]  77.74 90.71 180 top
C706  4.7UF  [0402]  69.49 90.71 0 top
C707  4.7UF  [0402]  80.15 90.33 270 top
C711  4.7UF  [0402]  111.83 100.51 90 bottom
C713  4.7UF  [0402]  122.68 100.51 90 top
C716  0.068UF  [0402]  80.66 71.15 180 top
C717  0.068UF  [0402]  73.93 64.93 90 top
C718  0.068UF  [0402]  67.58 70.01 270 top
C719  0.068UF  [0402]  74.06 71.15 180 top
C720  0.068UF  [0402]  73.95 92.43 90 top
C721  0.068UF  [0402]  74.06 99.35 180 top
C722  0.068UF  [0402]  80.66 99.35 180 top
C723  0.068UF  [0402]  67.58 98.2 270 top
C729  0.15UF  [0402]  179.23 133.02 0 bottom
C740  100PF  [0402]  176.03 140.56 180 bottom
C749  0.47UF  [0402]  78.49 71.14 180 top
C750  0.47UF  [0402]  81.3 62.14 270 top
C751  0.47UF  [0402]  75.2 62.52 0 top
C752  0.47UF  [0402]  71.77 71.15 180 top
C753  0.47UF  [0402]  81.3 90.33 270 top
C754  0.47UF  [0402]  75.2 90.71 0 top
C755  0.47UF  [0402]  71.77 99.35 180 top
C756  0.47UF  [0402]  78.49 99.33 180 top
C774  0.1UF  [0402]  27.94 115.87 0 bottom
C775  0.1UF  [0402]  27.43 126.03 0 bottom
C780  0.1UF  [0402]  15.45 114.79 270 top
C788  100UF  [1206]  30.4 128.17 270 bottom
C789  100UF  [1206]  13.87 146.83 90 top
C790  100UF  [1206]  16.66 146.83 90 top
C791  100UF  [1206]  19.46 146.83 90 top
C792  47UF  [1210]  4.24 125.63 180 top
C794  10UF  [0603]  17.96 142.6 180 bottom
C795  47UF  [1210]  24 147.42 90 top
C796  47UF  [1210]  30.53 128.27 270 top
C798  4.7UF  [0402]  23.85 128.03 270 bottom
C801  4.7UF  [0402]  21.01 126.75 0 bottom
C803  4.7UF  [0402]  22.73 143.89 0 bottom
C805  4.7UF  [0402]  22.78 142.04 180 bottom
C806  4.7UF  [0402]  10.28 126.8 0 bottom
C808  4.7UF  [0402]  12.37 126.8 0 bottom
C810  4.7UF  [0402]  16.31 129.47 90 bottom
C811  4.7UF  [0402]  16.56 126.75 0 bottom
C816  100UF  [1206]  4.24 125.76 180 bottom
C820  0.47UF  [0402]  18.72 126.8 0 bottom
C821  0.47UF  [0402]  10.16 142.62 180 bottom
C822  0.47UF  [0402]  18.21 134.11 0 bottom
C825  0.47UF  [0402]  7.16 141.02 90 top
C828  0.47UF  [0402]  12.61 142.63 0 bottom
C830  0.47UF  [0402]  13.26 134.16 180 bottom
C833  0.47UF  [0402]  8.31 127.51 270 bottom
C834  0.47UF  [0402]  14.86 142.88 180 bottom
C835  0.47UF  [0402]  16.31 136.96 270 bottom
C837  0.47UF  [0402]  7.92 129.67 270 bottom
C841  0.47UF  [0402]  16.31 139.07 90 bottom
C842  0.47UF  [0402]  7.8 138.81 90 bottom
C843  0.47UF  [0402]  16.31 132.72 270 bottom
C844  0.47UF  [0402]  7.16 141.02 90 bottom
C848  0.1UF  [0402]  162.63 21.28 90 bottom
C849  0.1UF  [0402]  163.39 17.49 180 bottom
C850  0.1UF  [0402]  162.51 19.12 90 bottom
C851  0.1UF  [0402]  166.44 21.53 90 bottom
C852  0.1UF  [0402]  165.56 17.44 0 bottom
C853  0.1UF  [0402]  166.56 19.31 90 bottom
C856  DNP  [C402-25]  112.24 71.35 180 bottom
C858  DNP  [C402-25]  122.73 70.84 90 bottom
C859  0.1UF  [0402]  35.71 108.84 0 bottom
C862  0.022UF  [0402]  38.56 103.5 0 bottom
C864  0.1UF  [0402]  12.89 120.21 270 bottom
C865  0.1UF  [0402]  7.96 119.82 270 bottom
C866  22UF  [1206]  17.84 119.7 0 bottom
C867  47UF  [1206]  7.96 120.58 270 top
C868  47UF  [1206]  5.17 120.58 270 top
C869  DNP  [0402]  35.46 112.93 90 bottom
C870  DNP  [0402]  35.51 110.74 270 bottom
C871  0.01UF  [0402]  223.39 150.15 180 bottom
C872  0.01UF  [0402]  16.91 117.26 0 top
C873  1UF  [0402]  29.74 106.55 270 bottom
C874  1UF  [0402]  41.63 109.01 90 bottom
C876  4.7UF  [0805]  38.96 109.01 0 bottom
C878  5600PF  [0402]  10.73 120.54 0 bottom
C879  560PF  [0402]  13.88 117.29 180 bottom
C891  1UF  [0603]  10.03 66.91 90 top
C892  1UF  [0603]  11.76 67.4 90 top
C893  0.1UF  [0402]  52.67 149.6 270 bottom
C894  0.1UF  [0402]  51.53 149.6 270 bottom
C895  100UF  [1210]  72.01 147.24 270 top
C896  100UF  [1210]  67.44 147.24 270 top
C902  100UF  [1206]  113.45 105.46 180 bottom
C903  100UF  [1206]  120.78 108.89 0 top
C905  100UF  [1210]  38.73 103.58 180 top
C906  100UF  [1206]  169.67 80.44 90 bottom
C907  100UF  [1206]  152.4 91.87 90 bottom
C908  100UF  [1206]  156.97 84.25 0 bottom
C909  100UF  [1206]  169.67 68.63 90 bottom
C910  1UF  [0603]  211.46 145.32 90 top
C911  470UF  [TANT_D]  109.46 121.04 90 top
C913  10UF  [0805]  26.21 140.08 180 bottom
C914  100UF  [1206]  169.67 62.15 270 bottom
C915  470UF  [TANT_D]  179.38 113.32 180 top
C916  100UF  [1206]  160.2 70.38 0 bottom
C917  100UF  [1206]  169.67 74.6 270 bottom
C918  100UF  [1206]  184.28 75.23 0 bottom
C919  4.7UF  [0402]  84.07 57.2 180 top
C920  4.7UF  [0402]  152.27 96.82 0 bottom
C921  4.7UF  [0402]  114.93 100.51 90 bottom
C922  4.7UF  [0402]  116.46 100.51 90 bottom
C923  4.7UF  [0402]  152.27 95.55 0 bottom
C924  4.7UF  [0402]  110.28 100.51 90 bottom
C953  0.1UF  [0402]  71.24 72.3 0 top
C954  0.1UF  [0402]  71.06 75.44 180 top
C955  0.1UF  [0402]  69.87 85.25 0 top
C956  100UF  [1210]  119.76 146.56 180 top
C957  100UF  [1210]  131.32 146.46 0 top
C1011  1UF  [0603]  131.73 155.32 270 bottom
C1012  1UF  [0603]  122.1 158.19 180 bottom
C1013  1UF  [0603]  128.06 155.32 270 bottom
C1052  4.7UF  [0402]  69.49 76.61 0 top
C1053  4.7UF  [0402]  77.23 76.61 0 top
C1054  4.7UF  [0402]  79.23 76.61 180 top
C1070  0.068UF  [0402]  80.66 85.25 180 top
C1071  0.068UF  [0402]  74 78.21 270 top
C1072  0.068UF  [0402]  74.06 85.25 180 top
C1073  0.068UF  [0402]  67.58 84.11 270 top
C1108  100PF  [0805]  183.39 162.31 180 bottom
C1109  100PF  [0805]  122.1 161.96 180 bottom
C1138  0.47UF  [0402]  72.79 76.52 0 top
C1139  0.47UF  [0402]  71.77 85.25 180 top
C1140  0.47UF  [0402]  75.2 76.52 0 top
C1141  0.47UF  [0402]  78.49 85.23 180 top
C1142  0.1UF  [0402]  147.07 102.16 180 top
C1143  0.1UF  [0402]  164.78 41.79 180 bottom
C1144  0.1UF  [0402]  164.9 44.44 0 bottom
C1145  0.1UF  [0402]  156.52 44.44 0 bottom
C1146  0.1UF  [0402]  167.44 56.87 0 bottom
C1147  0.1UF  [0402]  164.9 58.54 0 bottom
C1148  0.1UF  [0402]  156.52 58.54 0 bottom
C1149  0.1UF  [0402]  164.78 69.98 180 bottom
C1150  0.1UF  [0402]  164.9 72.63 0 bottom
C1151  0.1UF  [0402]  156.52 72.63 0 bottom
C1152  0.1UF  [0402]  164.78 84.06 180 bottom
C1153  0.1UF  [0402]  164.9 86.73 0 bottom
C1154  0.1UF  [0402]  156.52 86.73 0 bottom
C1155  0.1UF  [0402]  154.84 100.22 90 bottom
C1156  0.1UF  [0402]  162.84 104.03 90 bottom
C1157  0.1UF  [0402]  161.19 100.22 90 bottom
C1158  0.1UF  [0402]  153.03 100.13 0 top
C1159  0.1UF  [0402]  167.54 100.22 90 bottom
C1160  0.1UF  [0402]  156.52 30.09 0 bottom
C1161  0.1UF  [0402]  169.73 30.1 180 bottom
C1162  0.1UF  [0402]  164.9 30.09 0 bottom
C1163  0.01UF  [0402]  169.9 92.88 0 bottom
C1164  4.7UF  [0402]  144.91 102.16 0 top
C1165  4.7UF  [0402]  164.02 53.08 0 bottom
C1166  4.7UF  [0402]  155.69 53.08 0 bottom
C1167  4.7UF  [0402]  166.68 53.46 90 bottom
C1168  4.7UF  [0402]  164.02 67.17 0 bottom
C1169  4.7UF  [0402]  155.69 67.17 0 bottom
C1170  4.7UF  [0402]  166.68 67.55 90 bottom
C1171  4.7UF  [0402]  163.62 81.4 0 bottom
C1172  4.7UF  [0402]  155.69 81.4 0 bottom
C1173  4.7UF  [0402]  166.68 81.65 90 bottom
C1174  4.7UF  [0402]  155.69 95.49 0 bottom
C1175  4.7UF  [0402]  163.79 95.5 0 bottom
C1176  4.7UF  [0402]  166.68 95.75 90 bottom
C1177  4.7UF  [0402]  163.79 38.86 0 bottom
C1178  4.7UF  [0402]  155.69 38.85 0 bottom
C1179  4.7UF  [0402]  156.11 104.03 90 bottom
C1180  4.7UF  [0402]  167.54 104.03 90 bottom
C1181  4.7UF  [0402]  150.65 103.9 90 top
C1182  4.7UF  [0402]  166.68 39.11 90 bottom
C1183  10UF  [0805]  148.32 108.7 90 bottom
C1184  10UF  [0805]  152.37 108.7 90 bottom
C1185  10UF  [0805]  150.35 108.7 90 bottom
C1186  10UF  [0805]  144.19 109.66 180 bottom
C1187  10UF  [0805]  144.19 107.61 180 bottom
C1188  0.068UF  [0402]  159.86 53.08 0 bottom
C1189  0.068UF  [0402]  167.32 44.44 0 bottom
C1190  0.068UF  [0402]  161.86 45.71 270 bottom
C1191  0.068UF  [0402]  162.81 43.61 270 bottom
C1192  0.068UF  [0402]  162.89 57.77 270 bottom
C1193  0.068UF  [0402]  167.32 58.54 0 bottom
C1194  0.068UF  [0402]  159.86 67.17 0 bottom
C1195  0.068UF  [0402]  161.86 59.81 270 bottom
C1196  0.068UF  [0402]  159.71 81.4 0 bottom
C1197  0.068UF  [0402]  167.32 72.63 0 bottom
C1198  0.068UF  [0402]  161.86 73.9 270 bottom
C1199  0.068UF  [0402]  154.31 72.44 180 bottom
C1200  0.068UF  [0402]  161.98 89.02 90 bottom
C1201  0.068UF  [0402]  154.1 87.87 90 bottom
C1202  0.068UF  [0402]  159.86 95.5 0 bottom
C1203  0.068UF  [0402]  167 86.73 0 bottom
C1204  0.068UF  [0402]  167.32 30.09 0 bottom
C1205  0.068UF  [0402]  154.1 31.23 90 bottom
C1206  0.068UF  [0402]  161.86 31.36 270 bottom
C1207  0.068UF  [0402]  159.86 38.86 0 bottom
C1208  1000PF  [0402]  144.53 105.33 180 top
C1209  0.47UF  [0402]  161.98 53.08 0 bottom
C1210  0.47UF  [0402]  160.01 44.44 0 bottom
C1211  0.47UF  [0402]  156.78 48.25 0 bottom
C1212  0.47UF  [0402]  167.83 53.46 90 bottom
C1213  0.47UF  [0402]  161.98 67.17 0 bottom
C1214  0.47UF  [0402]  160.01 58.54 0 bottom
C1215  0.47UF  [0402]  167.83 67.55 90 bottom
C1216  0.47UF  [0402]  156.78 62.35 0 bottom
C1217  0.47UF  [0402]  167.83 81.65 90 bottom
C1218  0.47UF  [0402]  161.68 81.4 0 bottom
C1219  0.47UF  [0402]  156.78 76.44 0 bottom
C1220  0.47UF  [0402]  160.01 72.63 0 bottom
C1221  0.47UF  [0402]  161.86 95.49 0 bottom
C1222  0.47UF  [0402]  160.01 86.73 0 bottom
C1223  0.47UF  [0402]  167.83 95.75 90 bottom
C1224  0.47UF  [0402]  156.78 90.54 0 bottom
C1225  0.47UF  [0402]  167.83 39.11 90 bottom
C1226  0.47UF  [0402]  160.01 30.09 0 bottom
C1227  0.47UF  [0402]  156.78 33.9 0 bottom
C1228  0.47UF  [0402]  161.86 38.85 0 bottom
C1232  0.1UF  [0402]  102.64 119.57 0 top
C1233  0.1UF  [0402]  93.73 108.19 270 bottom
C1235  0.1UF  [0402]  67.21 113.85 0 top
C1236  0.1UF  [0402]  82.17 116.13 180 bottom
C1237  0.1UF  [0402]  84.23 110.29 270 bottom
C1238  0.1UF  [0402]  84.23 112.45 90 bottom
C1239  0.1UF  [0402]  84.23 117.91 90 bottom
C1240  0.1UF  [0402]  84.23 114.61 90 bottom
C1241  0.1UF  [0402]  84.23 119.95 90 bottom
C1242  0.1UF  [0402]  89.69 108.39 180 bottom
C1243  0.1UF  [0402]  93.09 125.65 90 bottom
C1244  0.1UF  [0402]  102.64 118.3 180 bottom
C1245  0.1UF  [0402]  102.52 122.74 90 bottom
C1246  0.1UF  [0402]  92.1 108.39 0 bottom
C1247  0.1UF  [0402]  59.93 131.42 90 top
C1269  4.7UF  [0402]  98.96 124.26 0 bottom
C1270  4.7UF  [0402]  84.99 122.87 0 top
C1271  4.7UF  [0402]  75.21 122.49 90 bottom
C1272  4.7UF  [0402]  75.15 108.26 0 bottom
C1273  4.7UF  [0402]  55.33 131.07 180 top
C1277  0.068UF  [0402]  90.96 116.26 180 bottom
C1279  0.068UF  [0402]  94.39 121.22 270 bottom
C1280  0.068UF  [0402]  101.25 122.74 90 bottom
C1281  0.068UF  [0402]  87.02 123.12 0 bottom
C1282  0.068UF  [0402]  96.29 116.39 0 bottom
C1283  0.068UF  [0402]  75.21 113.85 270 bottom
C1284  0.068UF  [0402]  75.21 110.93 270 bottom
C1285  0.068UF  [0402]  71.53 116.01 0 bottom
C1286  0.068UF  [0402]  79.91 116.01 180 bottom
C1287  0.068UF  [0402]  82.15 123.38 270 bottom
C1288  0.068UF  [0402]  69.63 109.31 180 bottom
C1289  1000PF  [0402]  54.63 136.38 180 bottom
C1290  0.47UF  [0402]  88.04 108.77 270 bottom
C1291  0.47UF  [0402]  87.91 116.26 180 bottom
C1292  0.47UF  [0402]  102.62 113.39 0 top
C1293  0.47UF  [0402]  96.8 124.26 0 bottom
C1294  0.47UF  [0402]  102.14 109.88 270 bottom
C1295  0.47UF  [0402]  86.26 110.93 270 bottom
C1296  0.47UF  [0402]  77.84 108.28 0 bottom
C1298  0.068UF  [0402]  94.52 112.33 90 bottom
C1299  0.47UF  [0402]  80.27 107.78 270 bottom
C1300  0.47UF  [0402]  81.54 107.78 270 bottom
C1301  0.47UF  [0402]  69.88 123.88 180 bottom
C1303  0.1UF  [0402]  143.36 21.64 270 top
C1304  0.1UF  [0402]  142.89 24.92 180 top
C1305  0.1UF  [0402]  143.36 21.64 270 bottom
C1306  0.1UF  [0402]  157.61 24.18 270 bottom
C1311  2.2UF  [0402]  46.54 117.5 180 bottom
C1313  10UF  [0603]  46.59 128.39 90 bottom
C1314  2.2UF  [0805]  38.78 126.13 180 top
C1315  22UF  [1210]  39.17 116.35 90 top
C1316  22UF  [1210]  35.87 116.35 90 top
C1317  1UF  [0603]  39.34 115.84 180 bottom
C1318  0.01UF  [0402]  40.69 119.91 270 bottom
C1325  0.22UF  [0402]  50.27 119.12 0 bottom
C1327  1000PF  [0402]  52.65 125.37 90 top
C1328  0.15UF  [0402]  40.69 124.23 270 bottom
C1329  0.15UF  [0402]  40.69 122.07 270 bottom
C1330  100PF  [0402]  48.24 127.43 90 bottom
C1331  DNP  [C402-25]  123.24 57.33 180 bottom
C1332  DNP  [C402-25]  137.24 53.35 0 bottom
C1336  4.7UF  [0603]  39.35 117.6 180 bottom
C1342  0.1UF  [0402]  57.46 118.3 270 top
C1343  0.1UF  [0402]  15.3 122.11 90 bottom
C1344  0.1UF  [0402]  58.88 24.06 180 bottom
C1345  0.1UF  [0402]  54.29 27.57 90 bottom
C1346  0.1UF  [0402]  52.07 25.07 270 bottom
C1347  0.1UF  [0402]  49 24.35 270 bottom
C1348  22UF  [1206]  63.74 120.07 270 top
C1349  22UF  [1206]  42.6 20.71 180 bottom
C1350  22UF  [1206]  42.6 30.61 180 bottom
C1351  22UF  [1206]  42.6 27.31 180 bottom
C1352  22UF  [1206]  42.6 24.01 180 bottom
C1353  47UF  [1206]  61.98 127.39 180 bottom
C1354  47UF  [1206]  61.98 124.6 180 bottom
C1356  0.01UF  [0402]  61.2 118.19 270 bottom
C1358  5600PF  [0402]  57.61 123.11 90 top
C1359  560PF  [0402]  59.52 118.68 180 bottom
C1361  0.1UF  [0402]  5.13 160.93 270 bottom
C1362  1UF  [0402]  6.53 160.93 270 bottom
C1363  0.1UF  [0402]  90.17 24.31 0 top
C1364  0.1UF  [0402]  90.17 25.45 0 top
C1386  10UF  [0805]  53.17 131.57 270 top
C1387  10UF  [0805]  53.17 131.57 270 bottom
C1388  10UF  [0805]  63.13 133.2 270 bottom
C1389  10UF  [0805]  60.98 133.2 270 bottom
C1390  10UF  [0805]  65.28 133.2 270 bottom
C1391  0.47UF  [0402]  72.77 109.27 180 bottom
C1392  0.47UF  [0402]  75.21 118.42 270 bottom
C1395  0.1UF  [0402]  152.22 120.29 180 bottom
C1396  0.1UF  [0402]  221.57 54.64 90 bottom
C1397  0.01UF  [0402]  105.49 28.07 270 top
C1398  0.01UF  [0402]  104.22 28.07 270 top
C1401  2.2UF  [0402]  157.53 119.99 0 bottom
C1402  2.2UF  [0402]  221.27 49.33 270 bottom
C1404  2.2UF  [0402]  193.76 28.23 270 bottom
C1406  100UF  [1210]  151.51 111.56 180 top
C1407  100UF  [1210]  152.73 118.01 0 top
C1408  10UF  [0603]  157.48 109.09 270 bottom
C1409  10UF  [0603]  210.37 49.38 180 bottom
C1411  10UF  [0603]  182.96 28.04 180 bottom
C1412  2.2UF  [0805]  164.36 110.34 0 top
C1413  2.2UF  [0805]  211.62 42.5 270 top
C1415  2.2UF  [0805]  192.62 16.03 90 bottom
C1419  100UF  [1206]  141.8 130.5 270 top
C1420  100UF  [1206]  62.06 84.34 90 bottom
C1421  100UF  [1206]  218.7 54.19 270 top
C1423  100UF  [1206]  169.16 34.85 270 bottom
C1424  100UF  [1206]  102.95 109.84 270 top
C1425  100UF  [1206]  89.28 126.03 180 bottom
C1426  100UF  [1206]  66.83 118.22 270 top
C1427  100UF  [1206]  66.56 110.26 270 top
C1428  100UF  [1206]  51.21 119.35 180 top
C1429  22UF  [1210]  164.26 123.67 270 top
C1430  22UF  [1210]  167.56 123.67 270 top
C1431  22UF  [1210]  225.59 42.6 180 top
C1432  22UF  [1210]  225.59 39.3 180 top
C1437  22UF  [1210]  182.37 21.89 0 top
C1438  22UF  [1210]  182.71 31.21 0 top
C1439  22UF  [1210]  182.71 34.51 0 top
C1440  22UF  [1210]  181.74 18.59 0 top
C1441  1UF  [0603]  174.54 18.14 270 bottom
C1442  1UF  [0603]  161.59 123.04 0 bottom
C1443  1UF  [0603]  224.32 45.26 270 bottom
C1445  1UF  [0603]  194.39 20.54 270 top
C1446  0.01UF  [0402]  163.37 117.57 90 bottom
C1447  0.01UF  [0402]  218.85 43.49 0 bottom
C1449  0.01UF  [0402]  190.96 20.54 270 bottom
C1450  4.7UF  [0402]  151.89 77.65 0 bottom
C1451  4.7UF  [0402]  84.07 63.3 180 top
C1452  4.7UF  [0402]  151.89 79.93 0 bottom
C1453  4.7UF  [0402]  151.89 78.79 0 bottom
C1454  4.7UF  [0402]  84.07 60.76 180 top
C1455  4.7UF  [0402]  151.89 81.08 0 bottom
C1462  4.7UF  [0402]  151.89 48.31 0 bottom
C1463  4.7UF  [0402]  151.89 45.9 0 bottom
C1464  4.7UF  [0402]  151.89 84.4 0 bottom
C1465  4.7UF  [0402]  151.89 70.92 0 bottom
C1466  4.7UF  [0402]  145.8 99.36 90 top
C1467  4.7UF  [0402]  151.89 40.18 0 bottom
C1474  4.7UF  [0402]  84.07 46.91 180 top
C1475  4.7UF  [0402]  143.64 31.67 270 top
C1476  4.7UF  [0402]  111.83 100.51 90 top
C1477  4.7UF  [0402]  143.64 31.67 270 bottom
C1478  4.7UF  [0402]  98.12 100.51 90 bottom
C1479  4.7UF  [0402]  93.04 100.51 90 top
C1480  4.7UF  [0402]  108.73 100.51 90 bottom
C1481  4.7UF  [0402]  142.37 31.67 270 top
C1483  4.7UF  [0402]  110.28 100.51 90 top
C1484  4.7UF  [0402]  104.09 100.51 90 top
C1485  4.7UF  [0402]  121.13 100.51 90 top
C1486  100UF  [1206]  162.31 55.04 0 bottom
C1487  47UF  [1210]  78.23 73.71 180 top
C1488  47UF  [1210]  76.58 87.81 180 top
C1504  0.22UF  [0402]  100.96 100.51 90 bottom
C1505  4.7UF  [0402]  84.07 49.45 180 top
C1506  0.22UF  [0402]  134.75 31.67 270 top
C1515  0.22UF  [0402]  136.02 31.67 270 top
C1516  0.22UF  [0402]  128.65 31.8 270 top
C1517  0.22UF  [0402]  109.47 31.8 270 bottom
C1518  0.22UF  [0402]  84.07 84.89 180 top
C1519  0.22UF  [0402]  84.07 45.64 180 top
C1520  0.22UF  [0402]  100.96 100.51 90 top
C1523  0.22UF  [0402]  153.8 118.36 180 bottom
C1524  0.22UF  [0402]  219.64 53.06 90 bottom
C1526  0.22UF  [0402]  193.12 31.85 90 bottom
C1527  2200PF  [0402]  149.9 114.52 90 top
C1528  2200PF  [0402]  212.89 55.42 180 top
C1530  2200PF  [0402]  194.52 44.17 0 bottom
C1531  0.15UF  [0402]  163.37 113.26 90 bottom
C1532  0.15UF  [0402]  163.37 115.42 90 bottom
C1533  0.15UF  [0402]  214.54 43.49 0 bottom
C1534  0.15UF  [0402]  216.7 43.49 0 bottom
C1537  0.15UF  [0402]  187.66 23.08 0 bottom
C1538  0.15UF  [0402]  190.2 22.32 0 bottom
C1539  100PF  [0402]  155.83 110.06 270 bottom
C1540  100PF  [0402]  211.34 51.03 180 bottom
C1542  1000PF  [0402]  183.6 29.81 180 bottom
C1543  4.7UF  [0603]  164.72 119.89 0 bottom
C1544  4.7UF  [0603]  221.17 42.14 270 bottom
C1546  4.7UF  [0603]  193.12 20.54 270 bottom
C1547  0.47UF  [0402]  98.12 100.51 90 top
C1548  0.47UF  [0402]  91.77 100.51 90 top
C1549  0.47UF  [0402]  90.5 100.51 90 top
C1550  0.47UF  [0402]  128.65 31.8 270 bottom
C1551  0.1UF  [0402]  58.88 49.63 180 bottom
C1552  0.1UF  [0402]  52.07 50.65 270 bottom
C1553  0.1UF  [0402]  49 49.92 270 bottom
C1554  22UF  [1206]  42.6 46.28 180 bottom
C1555  22UF  [1206]  42.6 52.88 180 bottom
C1556  22UF  [1206]  42.6 49.58 180 bottom
C1557  4.7UF  [0402]  84.07 79.81 180 top
C1558  4.7UF  [0402]  84.07 83.62 180 top
C1559  4.7UF  [0402]  84.07 87.43 180 top
C1566  0.1UF  [0402]  2.97 164.74 270 bottom
C1567  0.1UF  [0402]  16.31 134.88 270 bottom
C1568  4.7UF  [0402]  151.89 41.58 0 bottom
C1569  4.7UF  [0402]  151.89 44.63 0 bottom
C1570  4.7UF  [0402]  151.89 85.55 0 bottom
C1571  4.7UF  [0402]  151.89 72.06 0 bottom
C1572  4.7UF  [0402]  151.89 53.9 180 bottom
C1573  4.7UF  [0402]  151.89 43.1 0 bottom
C1574  4.7UF  [0402]  84.07 72.31 180 top
C1575  4.7UF  [0402]  151.89 76.63 0 bottom
C1576  4.7UF  [0402]  84.07 64.57 180 top
C1577  4.7UF  [0402]  84.07 62.03 180 top
C1578  0.47UF  [0402]  124.84 31.93 90 bottom
C1579  0.47UF  [0402]  25.53 138.23 180 bottom
C1580  0.1UF  [0402]  79.88 25.45 0 top
C1581  0.1UF  [0402]  79.88 24.31 0 top
C1582  0.1UF  [0402]  3.48 83.82 270 bottom
C1583  0.1UF  [0402]  7.09 87.76 180 bottom
C1584  0.1UF  [0402]  217.64 116.71 90 top
C1585  0.1UF  [0402]  217.64 114.55 270 top
C1586  0.1UF  [0402]  231 104.78 180 bottom
C1587  0.1UF  [0402]  236.52 116.23 90 bottom
C1588  0.1UF  [0402]  210.14 110.36 90 top
C1589  0.1UF  [0402]  217.64 104.14 270 top
C1590  0.1UF  [0402]  217.64 106.3 90 top
C1591  0.1UF  [0402]  210.14 99.95 90 top
C1592  0.1UF  [0402]  217.64 93.72 270 top
C1593  0.1UF  [0402]  217.64 95.88 90 top
C1594  0.1UF  [0402]  210.14 89.53 90 top
C1595  0.1UF  [0402]  184.95 59.37 180 top
C1596  0.1UF  [0402]  187.23 59.37 0 top
C1597  0.1UF  [0402]  174.38 51.77 90 top
C1598  0.1UF  [0402]  180.73 43.65 90 bottom
C1599  0.1UF  [0402]  181.62 65.64 90 top
C1600  0.1UF  [0402]  151.07 138.84 270 top
C1601  0.1UF  [0402]  151.07 141.12 90 top
C1602  0.1UF  [0402]  160.84 132.76 180 top
C1603  0.1UF  [0402]  168.72 139.87 180 bottom
C1604  0.1UF  [0402]  143.7 136.31 90 top
C1605  22UF  [1206]  222.97 114.3 0 bottom
C1606  22UF  [1206]  222.97 114.3 0 top
C1607  22UF  [1206]  222.97 117.22 0 top
C1608  22UF  [1206]  238.42 96.31 90 bottom
C1609  22UF  [1206]  222.97 106.8 0 top
C1610  22UF  [1206]  222.97 103.88 0 top
C1611  22UF  [1206]  222.97 103.88 0 bottom
C1612  22UF  [1206]  222.97 96.39 0 top
C1613  22UF  [1206]  222.97 93.47 0 bottom
C1614  22UF  [1206]  222.97 93.47 0 top
C1615  22UF  [1206]  183.2 52.3 270 bottom
C1616  22UF  [1206]  186.12 52.3 270 top
C1617  22UF  [1206]  172.01 56.8 270 top
C1618  22UF  [1206]  156.6 141.32 0 top
C1619  22UF  [1206]  156.6 138.4 0 bottom
C1620  22UF  [1206]  164.98 128.23 0 top
C1621  47UF  [1206]  186.12 52.3 270 bottom
C1622  47UF  [1206]  183.2 52.3 270 top
C1623  47UF  [1206]  156.6 138.4 0 top
C1624  47UF  [1206]  156.6 141.32 0 bottom
C1625  10UF  [0603]  55.34 172.2 180 bottom
C1626  10UF  [0603]  51.46 152.75 270 bottom
C1627  10UF  [0603]  125.39 161.32 270 bottom
C1628  10UF  [0603]  121.45 155.32 270 bottom
C1629  10UF  [0603]  229.53 96.18 270 bottom
C1630  10UF  [0603]  171.58 52.41 90 top
C1631  10UF  [0603]  160.21 129.46 180 top
C1632  10UF  [1210]  47.75 147.12 270 top
C1633  10UF  [1210]  138.3 146.35 0 top
C1634  2.2UF  [0805]  235.46 129.21 180 bottom
C1635  2.2UF  [0805]  179.38 58.46 270 bottom
C1636  2.2UF  [0805]  149.16 133.01 0 bottom
C1637  0.022UF  [0402]  225.72 101.13 0 bottom
C1638  0.022UF  [0402]  171.82 47.69 180 bottom
C1639  0.022UF  [0402]  164.67 130.96 270 bottom
C1640  1UF  [0603]  6.86 86.16 180 bottom
C1641  1UF  [0603]  51.98 160.69 180 bottom
C1642  1UF  [0603]  55.34 170.55 180 bottom
C1643  1UF  [0603]  55.34 168.77 180 bottom
C1644  1UF  [0603]  54.76 152.75 270 bottom
C1645  1UF  [0603]  56.41 152.75 270 bottom
C1646  1UF  [0603]  49.81 152.75 270 bottom
C1647  1UF  [0603]  53.11 152.75 270 bottom
C1648  1UF  [0603]  61.87 152.75 270 bottom
C1649  1UF  [0603]  124.75 170.21 180 bottom
C1650  1UF  [0603]  125.01 167.28 270 bottom
C1651  1UF  [0603]  122.1 159.95 180 bottom
C1652  1UF  [0603]  129.71 155.32 270 bottom
C1653  1UF  [0603]  123.1 155.32 270 bottom
